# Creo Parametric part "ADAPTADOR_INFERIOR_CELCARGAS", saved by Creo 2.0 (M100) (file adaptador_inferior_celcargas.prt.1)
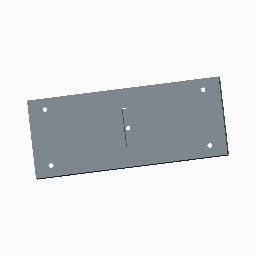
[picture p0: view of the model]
Units: millimeter Newton Second (mmNs); MM, TONNE, SECS

Created from: MMNS_PART_SOLID.PRT

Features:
  1. datum plane "RIGHT"
  2. datum plane "TOP"
  3. datum plane "FRONT"
  4. coordinate system
  5. sketch "Sketch 1"
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
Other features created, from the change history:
  extrusion "Extrude 1"
  sketch "Sketch 2"
  extruded cut "Extrude 2"
  sketch "Sketch 3"
  extruded cut "Extrude 3"
  sketch "Sketch 4"
  extruded cut "Extrude 4"
  sketch "Sketch 5"
  extruded cut "Extrude 5"
  sketch "Sketch 6"
  extruded cut "Extrude 6"
  sketch "Sketch 7"
  extruded cut "Extrude 7"

Surfaces: 14 plane, 10 cylinder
